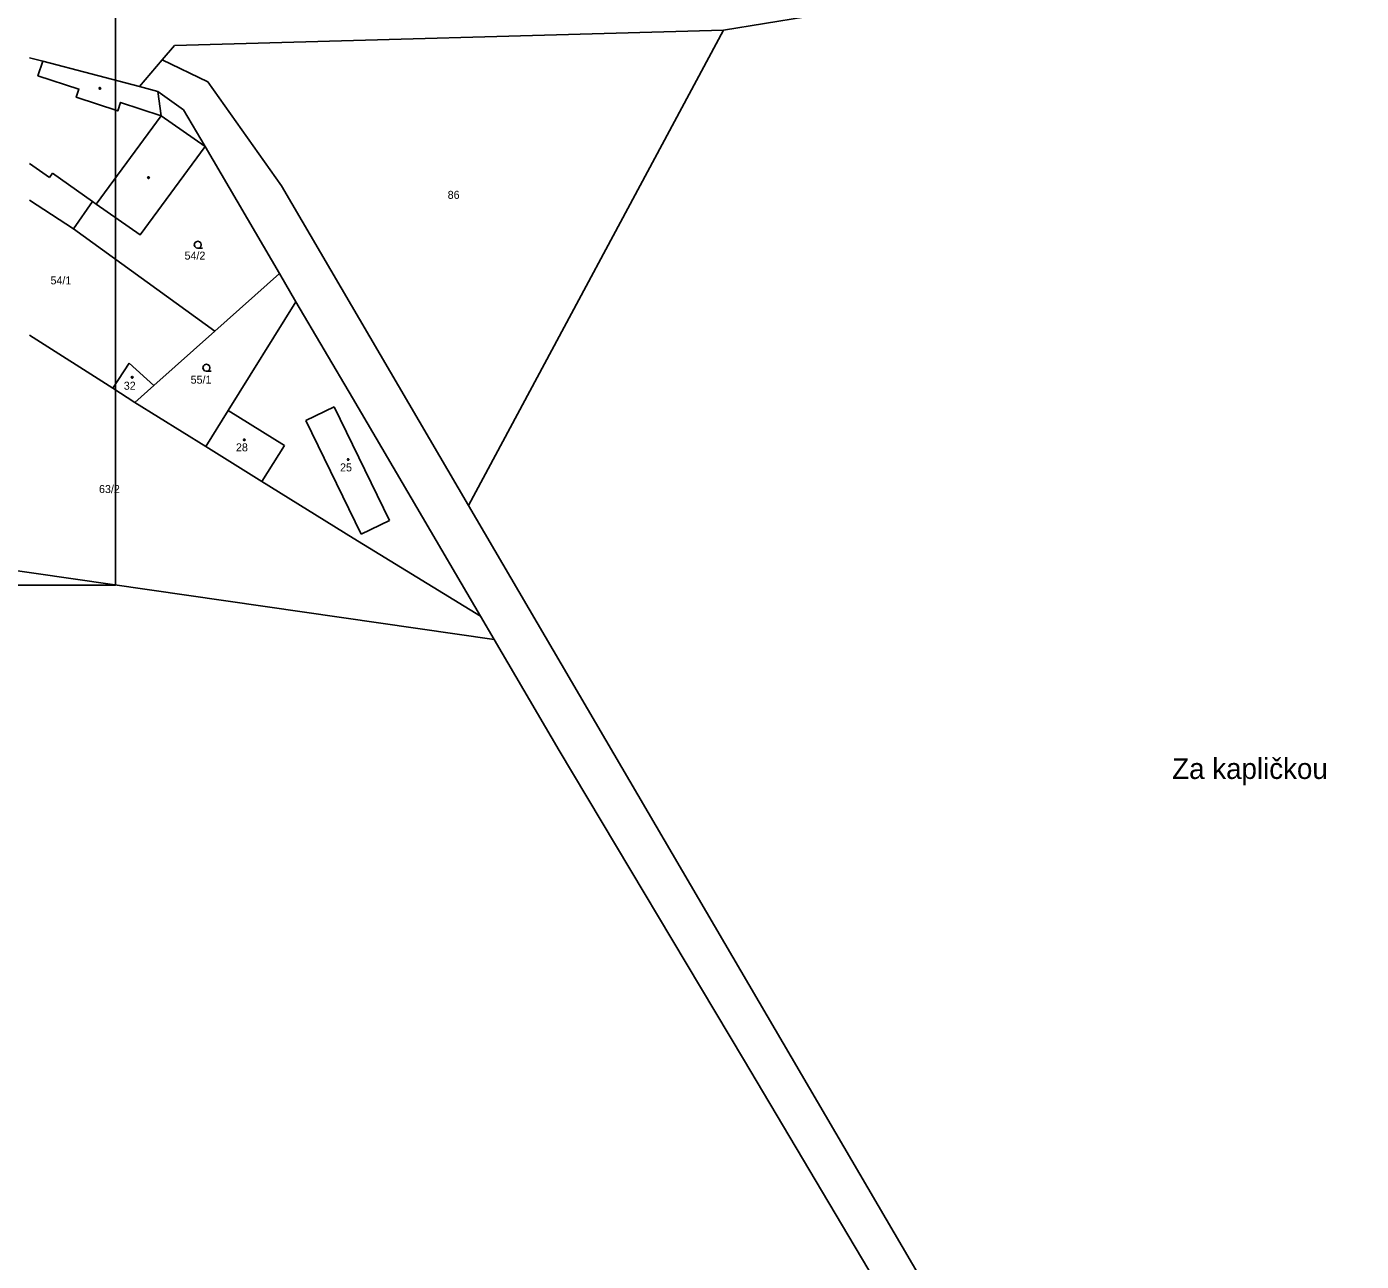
# Model space of a CAD drawing. Extents: x -752343 to -750336, y -1035826 to -1033329.
# Drawn here: x -751372.1 to -751088.6, y -1034703.4 to -1034441.1 of the extents above; entities that cross this region are included whole.
import ezdxf

# ---------------------------------------------------------------- set-up
doc = ezdxf.new("R2010")
doc.units = 0
for name, color, linetype in [('Default', 7, 'Continuous'), ('KN_HRANICE', 7, 'Continuous'), ('KN_KULTURY', 7, 'Continuous'), ('KN_PARCELY', 7, 'Continuous'), ('KN_SLUCKY', 7, 'Continuous'), ('LEGENDA', 7, 'Continuous')]:
    doc.layers.add(name, color=color, linetype=linetype)

# ---------------------------------------------------------------- blocks, each defined once
blk = doc.blocks.new('304')
at = {"layer": 'Default'}
blk.add_lwpolyline([(0, 0), (-0.38, 0.1), (-0.65, 0.37), (-0.75, 0.74), (-0.65, 1.11), (-0.38, 1.38), (-0.01, 1.48), (0.36, 1.38), (0.63, 1.11), (0.73, 0.73), (0.63, 0.35), (0.36, 0.08), (-0.02, -0.02), (0.98, -0.02)], dxfattribs=at)
blk = doc.blocks.new('402')
at = {"layer": 'Default'}
blk.add_lwpolyline([(0.09, 0.15), (0.18, 0), (0.09, -0.15), (-0.09, -0.15), (-0.18, 0), (-0.09, 0.15), (0.09, 0.15)], dxfattribs=at)

msp = doc.modelspace()

# ---------------------------------------------------------------- linework, layer by layer
at = {"layer": 'KN_HRANICE'}
for p, q in [((-751060.35, -1034415.09), (-751224.07, -1034441.83)), ((-751340.67, -1034445.11), (-751224.07, -1034441.83)), ((-751224.07, -1034441.83), (-751278.23, -1034542.79)), ((-751343.26, -1034448.14), (-751340.67, -1034445.11)), ((-751371.43, -1034447.7), (-751368.66, -1034448.43)), ((-751368.66, -1034448.43), (-751348.13, -1034453.84)), ((-751343.26, -1034448.14), (-751348.13, -1034453.84)), ((-751333.6, -1034452.8), (-751343.26, -1034448.14)), ((-751317.95, -1034474.89), (-751333.6, -1034452.8)), ((-751348.13, -1034453.84), (-751344.2, -1034454.87)), ((-751344.2, -1034454.87), (-751338.77, -1034458.75)), ((-751334.18, -1034466.57), (-751338.77, -1034458.75)), ((-751334.18, -1034466.57), (-751318.36, -1034493.56)), ((-751278.23, -1034542.79), (-751317.95, -1034474.89)), ((-751371.43, -1034477.97), (-751362.12, -1034484.02)), ((-751358.06, -1034478.25), (-751362.12, -1034484.02)), ((-751357.31, -1034478.78), (-751358.06, -1034478.25)), ((-751332.1, -1034505.79), (-751362.12, -1034484.02)), ((-751332.1, -1034505.79), (-751318.36, -1034493.56)), ((-751318.36, -1034493.56), (-751314.87, -1034499.52)), ((-751329.25, -1034522.61), (-751314.87, -1034499.52)), ((-751314.87, -1034499.52), (-751302.9, -1034519.93)), ((-751371.43, -1034506.62), (-751353.74, -1034517.86)), ((-751345.07, -1034517.33), (-751332.1, -1034505.79)), ((-751353.74, -1034517.86), (-751350.28, -1034512.59)), ((-751350.28, -1034512.59), (-751345.07, -1034517.33)), ((-751349.09, -1034520.91), (-751353.74, -1034517.86)), ((-751349.09, -1034520.91), (-751345.07, -1034517.33)), ((-751349.09, -1034520.91), (-751334.03, -1034530.29)), ((-751302.9, -1034519.93), (-751289.24, -1034543.22)), ((-751334.03, -1034530.29), (-751329.25, -1034522.61)), ((-751329.25, -1034522.61), (-751317.32, -1034530.04)), ((-751322.1, -1034537.72), (-751334.03, -1034530.29)), ((-751317.32, -1034530.04), (-751322.1, -1034537.72)), ((-751302.76, -1034549.77), (-751322.1, -1034537.72)), ((-751289.24, -1034543.22), (-751275.68, -1034566.35)), ((-751161.12, -1034742.97), (-751278.23, -1034542.79)), ((-751302.76, -1034549.77), (-751275.68, -1034566.35)), ((-751397.73, -1034553.31), (-751272.79, -1034571.27)), ((-751275.68, -1034566.35), (-751272.79, -1034571.27)), ((-751272.79, -1034571.27), (-751258.95, -1034594.87)), ((-751258.95, -1034594.87), (-751219.84, -1034660.39)), ((-751219.84, -1034660.39), (-751168.66, -1034746.67))]:
    msp.add_line(p, q, dxfattribs=at)
msp.add_lwpolyline([(-751334.18, -1034466.57), (-751347.98, -1034485.33), (-751357.31, -1034478.78)], dxfattribs=at)
at = {"layer": 'KN_SLUCKY'}
for p, q in [((-751343.51, -1034460.01), (-751344.2, -1034454.87)), ((-751343.51, -1034460.01), (-751357.31, -1034478.78)), ((-751343.51, -1034460.01), (-751334.18, -1034466.57)), ((-751371.43, -1034470.19), (-751367.24, -1034473.14)), ((-751367.24, -1034473.14), (-751366.61, -1034472.24)), ((-751366.61, -1034472.24), (-751358.06, -1034478.25)), ((-751312.79, -1034524.74), (-751306.79, -1034521.82)), ((-751306.79, -1034521.82), (-751295.04, -1034546.03)), ((-751312.79, -1034524.74), (-751301.02, -1034548.93)), ((-751295.04, -1034546.03), (-751301.02, -1034548.93))]:
    msp.add_line(p, q, dxfattribs=at)
msp.add_lwpolyline([(-751368.66, -1034448.43), (-751369.67, -1034451.51), (-751360.98, -1034454.37), (-751361.54, -1034456.08), (-751352.71, -1034458.99), (-751352.12, -1034457.18), (-751343.51, -1034460.01)], dxfattribs=at)
at = {"layer": 'LEGENDA'}
msp.add_lwpolyline([(-751353.18, -1034559.75), (-751947.18, -1034559.75), (-751947.18, -1034139.75), (-751353.18, -1034139.75)], close=True, dxfattribs=at)

# ---------------------------------------------------------------- block references
at = {"layer": 'KN_KULTURY'}
for name, p in [('402', (-751356.52, -1034454.19)), ('402', (-751346.19, -1034473.18)), ('304', (-751335.71, -1034488.16)), ('304', (-751333.89, -1034514.28)), ('402', (-751349.66, -1034515.59)), ('402', (-751325.85, -1034528.86)), ('402', (-751303.78, -1034533.04))]:
    msp.add_blockref(name, p, dxfattribs=at)

# ---------------------------------------------------------------- texts
at = {"layer": 'KN_PARCELY'}
for s, height, p in [('86', 1.7, (-751282.66, -1034477.67)), ('54/2', 1.7, (-751338.54, -1034490.58)), ('54/1', 1.7, (-751367, -1034495.84)), ('55/1', 1.7, (-751337.24, -1034516.93)), ('32', 1.7, (-751351.44, -1034518.22)), ('28', 1.7, (-751327.62, -1034531.31)), ('25', 1.7, (-751305.51, -1034535.57)), ('63/2', 1.7, (-751356.7, -1034540.17)), ('Za kapličkou', 4.4, (-751128.8, -1034600.9))]:
    msp.add_text(s, height=height, dxfattribs=at).set_placement(p)

doc.saveas('drawing.dxf')
